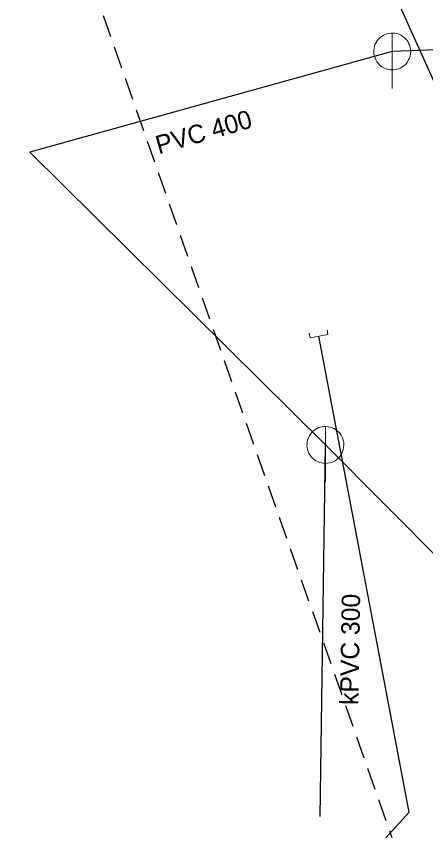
# Model space of a CAD drawing. Extents: x -659250 to -657316, y -997555 to -993684.
# Drawn here: x -658211.09 to -658188.9, y -996491.07 to -996446.96 of the extents above; entities that cross this region are included whole.
import ezdxf

# ---------------------------------------------------------------- set-up
doc = ezdxf.new("R2010")
doc.units = 0
doc.header["$LTSCALE"] = 0.4
doc.linetypes.add('MEDIUM_DASHED', pattern=[4.5, 3, -1.5])
doc.layers.add('1', color=7, linetype='Continuous')
for name, color, linetype, lineweight in [('14', 7, 'Continuous', 25), ('17', 7, 'Continuous', 25), ('22', 7, 'Continuous', 13), ('47', 7, 'Continuous', 13), ('63', 7, 'MEDIUM_DASHED', 25)]:
    doc.layers.add(name, color=color, linetype=linetype, lineweight=lineweight)

msp = doc.modelspace()

# ---------------------------------------------------------------- linework, layer by layer
at = {"layer": '14'}
for p, q in [((-658148.079, -996447.25), (-658190.719, -996448.87)), ((-658190.719, -996448.87), (-658210.35, -996454.32)), ((-658194.34, -996470.18), (-658210.35, -996454.32)), ((-658194.629, -996490.309), (-658194.34, -996470.18)), ((-658153.802, -996510.91), (-658194.34, -996470.18))]:
    msp.add_line(p, q, dxfattribs=at)
at = {"layer": '17'}
for points in [[(-658187.677, -996452.73), (-658187.756, -996452.037), (-658193.366, -996439.601), (-658202.822, -996415.717), (-658204.513, -996411.723), (-658210.651, -996397.227), (-658216.25, -996384.063), (-658217.364, -996381.052), (-658220.46, -996373.316), (-658223.436, -996366.695), (-658223.489, -996366.02), (-658224.153, -996365.028), (-658230.886, -996355.498), (-658241.289, -996342), (-658242.23, -996340.93)], [(-658228.921, -996510.517), (-658201.397, -996503.535), (-658195.019, -996495.802), (-658192.708, -996493.263), (-658189.798, -996490.063), (-658194.688, -996464.282)]]:
    msp.add_lwpolyline(points, dxfattribs=at)
at = {"layer": '22'}
for p, q in [((-658190.719, -996450.87), (-658190.718, -996447.87)), ((-658194.34, -996472.18), (-658194.339, -996469.18))]:
    msp.add_line(p, q, dxfattribs=at)
for points in [[(-658189.719, -996448.87), (-658189.724, -996448.761), (-658189.742, -996448.653), (-658189.772, -996448.547), (-658189.812, -996448.446), (-658189.864, -996448.349), (-658189.926, -996448.259), (-658189.998, -996448.176), (-658190.078, -996448.102), (-658190.166, -996448.036), (-658190.26, -996447.981), (-658190.36, -996447.936), (-658190.465, -996447.903), (-658190.572, -996447.881), (-658190.681, -996447.871), (-658190.791, -996447.873), (-658190.899, -996447.887), (-658191.006, -996447.912), (-658191.109, -996447.949), (-658191.207, -996447.998), (-658191.299, -996448.056), (-658191.385, -996448.125), (-658191.462, -996448.202), (-658191.531, -996448.288), (-658191.59, -996448.38), (-658191.638, -996448.478), (-658191.675, -996448.581), (-658191.701, -996448.688), (-658191.715, -996448.796), (-658191.718, -996448.906), (-658191.708, -996449.015), (-658191.687, -996449.122), (-658191.653, -996449.226), (-658191.609, -996449.326), (-658191.554, -996449.421), (-658191.488, -996449.509), (-658191.414, -996449.589), (-658191.331, -996449.661), (-658191.241, -996449.723), (-658191.145, -996449.775), (-658191.043, -996449.816), (-658190.938, -996449.846), (-658190.83, -996449.864), (-658190.72, -996449.87), (-658190.611, -996449.864), (-658190.503, -996449.846), (-658190.398, -996449.817), (-658190.296, -996449.776), (-658190.199, -996449.724), (-658190.109, -996449.662), (-658190.026, -996449.591), (-658189.951, -996449.511), (-658189.886, -996449.423), (-658189.83, -996449.329), (-658189.786, -996449.229), (-658189.752, -996449.125), (-658189.73, -996449.017), (-658189.72, -996448.908)], [(-658193.34, -996470.18), (-658193.345, -996470.071), (-658193.363, -996469.963), (-658193.393, -996469.857), (-658193.433, -996469.756), (-658193.485, -996469.659), (-658193.547, -996469.569), (-658193.619, -996469.486), (-658193.699, -996469.412), (-658193.787, -996469.346), (-658193.881, -996469.291), (-658193.981, -996469.246), (-658194.086, -996469.213), (-658194.193, -996469.191), (-658194.302, -996469.181), (-658194.412, -996469.183), (-658194.52, -996469.197), (-658194.627, -996469.222), (-658194.73, -996469.259), (-658194.828, -996469.308), (-658194.92, -996469.366), (-658195.006, -996469.435), (-658195.083, -996469.512), (-658195.152, -996469.598), (-658195.211, -996469.69), (-658195.259, -996469.788), (-658195.296, -996469.891), (-658195.322, -996469.998), (-658195.336, -996470.106), (-658195.339, -996470.216), (-658195.329, -996470.325), (-658195.308, -996470.432), (-658195.274, -996470.536), (-658195.23, -996470.636), (-658195.175, -996470.731), (-658195.109, -996470.819), (-658195.035, -996470.899), (-658194.952, -996470.971), (-658194.862, -996471.033), (-658194.766, -996471.085), (-658194.664, -996471.126), (-658194.559, -996471.156), (-658194.451, -996471.174), (-658194.341, -996471.18), (-658194.232, -996471.174), (-658194.124, -996471.156), (-658194.019, -996471.127), (-658193.917, -996471.086), (-658193.82, -996471.034), (-658193.73, -996470.972), (-658193.647, -996470.901), (-658193.572, -996470.821), (-658193.507, -996470.733), (-658193.451, -996470.639), (-658193.407, -996470.539), (-658193.373, -996470.435), (-658193.351, -996470.327), (-658193.341, -996470.218)]]:
    msp.add_lwpolyline(points, close=True, dxfattribs=at)
at = {"layer": '47'}
msp.add_lwpolyline([(-658194.247, -996463.941), (-658194.2, -996464.189), (-658195.175, -996464.374), (-658195.222, -996464.126)], dxfattribs=at)
at = {"layer": '63'}
msp.add_lwpolyline([(-659116.685, -993855.266), (-658551.464, -993848.288), (-658551.464, -993848.288), (-657316.352, -997490.822), (-657316.352, -997490.822), (-657839.705, -997490.822), (-657839.705, -997490.822)], close=True, dxfattribs=at)

# ---------------------------------------------------------------- texts
at = {"layer": '1'}
for s, rotation, p in [('PVC 400 ', 16, (-658203.375, -996454.444)), ('kPVC 300', 89, (-658192.556, -996484.272))]:
    msp.add_text(s, height=1, rotation=rotation, dxfattribs=at).set_placement(p)

doc.saveas('drawing.dxf')
